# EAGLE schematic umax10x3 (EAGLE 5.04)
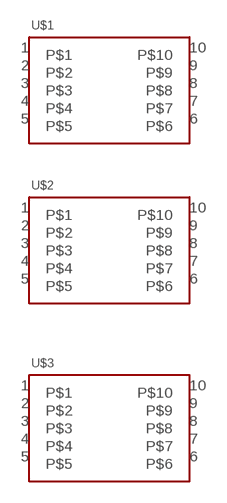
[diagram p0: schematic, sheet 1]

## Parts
U$1  SMD-ADAPTER-UMAX10  [SMD-DIP-ADAPTER-UMAX10]
U$2  SMD-ADAPTER-UMAX10  [SMD-DIP-ADAPTER-UMAX10]
U$3  SMD-ADAPTER-UMAX10  [SMD-DIP-ADAPTER-UMAX10]
Unconnected: U$1.1 U$1.2 U$1.3 U$1.4 U$1.5 U$1.6 U$1.7 U$1.8 U$1.9 U$1.10 U$2.1 U$2.2 U$2.3 U$2.4 U$2.5 U$2.6 U$2.7 U$2.8 U$2.9 U$2.10 U$3.1 U$3.2 U$3.3 U$3.4 U$3.5 U$3.6 U$3.7 U$3.8 U$3.9 U$3.10

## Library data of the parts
U$1-U$3 = trl:SMD-ADAPTER-UMAX10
